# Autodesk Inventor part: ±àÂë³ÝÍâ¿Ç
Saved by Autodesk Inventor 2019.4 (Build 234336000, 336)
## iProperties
Created: 2020-05
Part Number: ±àÂë³ÝÍâ¿Ç
Material: Generic
Document SubType Name: Modeling
Designer: Administrator
Density: 1 g/cm^3
Appearance: Default
Title: ±àÂë³ÝÍâ¿Ç
Author: Administrator
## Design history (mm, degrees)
feature "Body1"
body "Solid1"
